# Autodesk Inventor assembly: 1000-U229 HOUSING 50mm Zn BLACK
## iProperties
Created: 2007-03
Part Number: 1000-U229 HOUSING 50mm Zn BLACK
Document SubType Name: Assembly
Designer: Andy Moles
Translation Standard: STEP AP214IS
File Name: 1000-U68_ASM
Preprocessor: PRO/ENGINEER BY PARAMETRIC TECHNOLOGY CORPORATION, 2003200
Postprocessor: Build: 344b, Release: 11 SP2 - Date: Fri 08/18/2006
Sent Units: MILLIMETERS
Uncertainty: 0.007199712
Author: Andy Moles
